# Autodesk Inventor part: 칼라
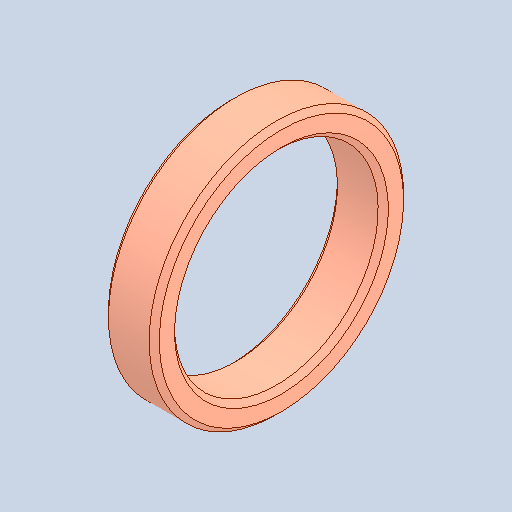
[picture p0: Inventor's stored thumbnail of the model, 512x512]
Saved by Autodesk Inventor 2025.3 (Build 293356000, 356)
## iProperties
Created: 2025-09
Part Number: 칼라
Material: 강철, 연강
Document SubType Name: Modeling
Designer: PC-15
Density: 7.85 g/cm^3
Appearance: 기본값
Author: jhkim
Sending System: Autodesk Inventor 2026
Preprocessor: ST-DEVELOPER v20.1
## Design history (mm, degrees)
feature "솔리드1"
node "솔리드2"
